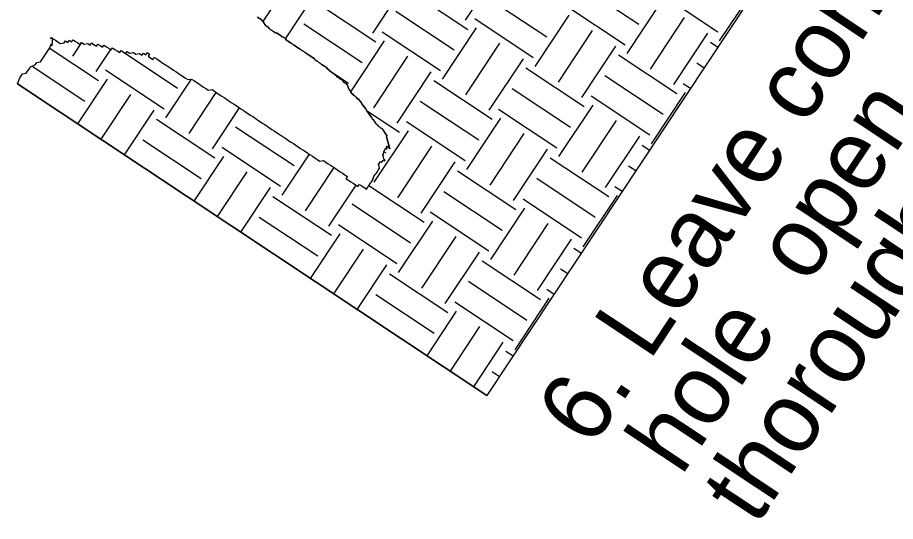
# Model space of a CAD drawing. Extents: x 561231 to 564935, y 589159 to 602519.
# Drawn here: x 564402.6 to 564452.8, y 589700.8 to 589729.7 of the extents above; entities that cross this region are included whole.
import ezdxf

# ---------------------------------------------------------------- set-up
doc = ezdxf.new("R2010")
doc.units = 0
doc.layers.add('Old_Level_1', color=7, linetype='Continuous')

msp = doc.modelspace()

# ---------------------------------------------------------------- linework, layer by layer
at = {"layer": 'Old_Level_1'}
for p, q in [((564452.672, 589743.055), (564429.449, 589708.039)), ((564428.21, 589729.508), (564430.164, 589732.454)), ((564416.632, 589729.431), (564418.251, 589731.874)), ((564422.911, 589728.782), (564424.865, 589731.728)), ((564434.797, 589731.501), (564438.142, 589729.281)), ((564417.91, 589728.453), (564419.589, 589730.986)), ((564425.004, 589731.211), (564428.349, 589728.992)), ((564439.329, 589731.071), (564442.674, 589728.851)), ((564442.775, 589728.328), (564444.728, 589731.274)), ((564419.743, 589730.492), (564423.089, 589728.272)), ((564429.536, 589730.781), (564432.881, 589728.562)), ((564434.015, 589730.322), (564437.361, 589728.103)), ((564437.476, 589727.602), (564439.43, 589730.548)), ((564424.223, 589730.033), (564427.568, 589727.813)), ((564432.201, 589726.86), (564434.154, 589729.806)), ((564418.962, 589729.313), (564422.307, 589727.094)), ((564428.755, 589729.603), (564432.1, 589727.383)), ((564438.814, 589726.715), (564440.768, 589729.66)), ((564423.441, 589728.855), (564426.786, 589726.635)), ((564426.902, 589726.135), (564428.856, 589729.08)), ((564433.539, 589725.972), (564435.493, 589728.918)), ((564404.451, 589728.446), (564404.503, 589728.523)), ((564421.645, 589725.421), (564423.581, 589728.338)), ((564440.152, 589725.827), (564442.106, 589728.772)), ((564404.382, 589727.926), (564407.201, 589726.056)), ((564405.724, 589727.46), (564406.24, 589728.238)), ((564407.062, 589726.572), (564407.897, 589727.832)), ((564408.488, 589727.779), (564411.733, 589725.626)), ((564428.24, 589725.247), (564430.194, 589728.192)), ((564434.877, 589725.085), (564436.83, 589728.031)), ((564442.245, 589728.256), (564442.67, 589727.974)), ((564422.965, 589724.505), (564424.919, 589727.45)), ((564429.578, 589724.359), (564431.532, 589727.304)), ((564436.984, 589727.536), (564440.33, 589725.316)), ((564403.393, 589726.886), (564406.42, 589724.878)), ((564431.671, 589726.788), (564435.016, 589724.568)), ((564441.464, 589727.078), (564441.889, 589726.796)), ((564407.606, 589726.667), (564410.952, 589724.448)), ((564420.429, 589726.643), (564421.526, 589725.916)), ((564424.303, 589723.617), (564426.257, 589726.562)), ((564436.203, 589726.358), (564439.548, 589724.138)), ((564429.449, 589708.039), (564402.563, 589725.877)), ((564402.563, 589725.877), (564429.449, 589708.039)), ((564429.449, 589708.039), (564402.563, 589725.877)), ((564406.012, 589723.588), (564407.708, 589726.144)), ((564411.053, 589723.925), (564412.526, 589726.145)), ((564426.41, 589726.068), (564429.755, 589723.849)), ((564440.682, 589725.899), (564441.107, 589725.618)), ((564407.351, 589722.701), (564409.046, 589725.256)), ((564412.391, 589723.037), (564413.946, 589725.381)), ((564430.89, 589725.609), (564434.235, 589723.39)), ((564438.868, 589722.437), (564440.822, 589725.383)), ((564425.629, 589724.89), (564428.974, 589722.67)), ((564435.422, 589725.179), (564438.767, 589722.96)), ((564408.689, 589721.813), (564410.384, 589724.369)), ((564413.729, 589722.149), (564415.284, 589724.494)), ((564422.55, 589724.356), (564424.442, 589723.1)), ((564430.108, 589724.431), (564433.453, 589722.212)), ((564433.57, 589721.711), (564435.523, 589724.657)), ((564410.523, 589723.852), (564413.868, 589721.632)), ((564428.294, 589720.969), (564430.248, 589723.915)), ((564434.908, 589720.823), (564436.861, 589723.769)), ((564415.055, 589723.422), (564418.4, 589721.202)), ((564424.847, 589723.712), (564428.192, 589721.492)), ((564422.996, 589720.243), (564424.949, 589723.188)), ((564429.632, 589720.082), (564431.586, 589723.027)), ((564436.246, 589719.935), (564438.199, 589722.881)), ((564409.742, 589722.674), (564413.087, 589720.454)), ((564414.273, 589722.244), (564417.618, 589720.024)), ((564424.334, 589719.355), (564426.287, 589722.301)), ((564438.338, 589722.365), (564438.763, 589722.083)), ((564417.72, 589719.501), (564419.275, 589721.846)), ((564423.538, 589722.004), (564423.661, 589721.922)), ((564430.97, 589719.194), (564432.924, 589722.139)), ((564412.68, 589719.165), (564414.375, 589721.721)), ((564425.672, 589718.467), (564427.625, 589721.413)), ((564433.077, 589721.645), (564436.422, 589719.425)), ((564414.018, 589718.277), (564415.713, 589720.833)), ((564419.058, 589718.614), (564420.693, 589721.078)), ((564427.764, 589720.896), (564431.109, 589718.677)), ((564437.557, 589721.186), (564437.982, 589720.905)), ((564432.296, 589720.466), (564435.641, 589718.247)), ((564415.356, 589717.39), (564417.051, 589719.945)), ((564420.396, 589717.726), (564421.951, 589720.07)), ((564422.687, 589720.056), (564425.848, 589717.957)), ((564436.775, 589720.008), (564437.2, 589719.726)), ((564417.19, 589719.429), (564420.535, 589717.209)), ((564426.983, 589719.718), (564430.328, 589717.499)), ((564431.514, 589719.288), (564434.86, 589717.069)), ((564434.961, 589716.546), (564436.915, 589719.492)), ((564421.722, 589718.999), (564425.067, 589716.779)), ((564429.662, 589715.82), (564431.616, 589718.765)), ((564416.409, 589718.25), (564419.754, 589716.031)), ((564426.201, 589718.54), (564429.546, 589716.321)), ((564420.94, 589717.82), (564424.286, 589715.601)), ((564424.387, 589715.078), (564426.341, 589718.024)), ((564431, 589714.932), (564432.954, 589717.877)), ((564419.347, 589714.742), (564421.042, 589717.297)), ((564425.725, 589714.19), (564427.679, 589717.136)), ((564432.338, 589714.044), (564434.292, 589716.99)), ((564420.685, 589713.854), (564422.38, 589716.41)), ((564427.063, 589713.303), (564429.017, 589716.248)), ((564434.431, 589716.473), (564434.856, 589716.192)), ((564429.17, 589715.753), (564432.516, 589713.534)), ((564422.023, 589712.966), (564423.718, 589715.522)), ((564433.65, 589715.295), (564434.074, 589715.013)), ((564423.857, 589715.005), (564427.203, 589712.786)), ((564428.389, 589714.575), (564431.735, 589712.356)), ((564423.076, 589713.827), (564426.421, 589711.608)), ((564432.868, 589714.117), (564433.293, 589713.835)), ((564427.607, 589713.397), (564430.953, 589711.178)), ((564431.054, 589710.655), (564433.007, 589713.601)), ((564426.014, 589710.318), (564427.709, 589712.874)), ((564427.352, 589709.43), (564429.047, 589711.987)), ((564428.69, 589708.543), (564430.385, 589711.099)), ((564430.524, 589710.582), (564430.949, 589710.3)), ((564429.743, 589709.404), (564430.168, 589709.122))]:
    msp.add_line(p, q, dxfattribs=at)
for points in [[(564416.314, 589729.685), (564416.383, 589729.64), (564416.452, 589729.594), (564416.52, 589729.549), (564416.568, 589729.474), (564416.637, 589729.428), (564416.685, 589729.352), (564416.734, 589729.277), (564416.783, 589729.201), (564416.85, 589729.156), (564416.919, 589729.11), (564416.968, 589729.035), (564417.036, 589728.99), (564417.139, 589728.921), (564417.207, 589728.876), (564417.276, 589728.831), (564417.344, 589728.785), (564417.432, 589728.77), (564417.501, 589728.724), (564417.603, 589728.656), (564417.706, 589728.588), (564417.775, 589728.543), (564417.844, 589728.497), (564417.912, 589728.452), (564417.995, 589728.353), (564418.063, 589728.308), (564418.131, 589728.262), (564418.2, 589728.217), (564418.268, 589728.172), (564418.337, 589728.126), (564418.405, 589728.081), (564418.474, 589728.035), (564418.542, 589727.99), (564418.645, 589727.922), (564418.713, 589727.877), (564418.782, 589727.831), (564418.85, 589727.786), (564418.953, 589727.718), (564419.022, 589727.672), (564419.09, 589727.627), (564419.192, 589727.559), (564419.261, 589727.513), (564419.329, 589727.468), (564419.397, 589727.423), (564419.5, 589727.354), (564419.569, 589727.309), (564419.617, 589727.234), (564419.686, 589727.188), (564419.754, 589727.143), (564419.823, 589727.097), (564419.891, 589727.052), (564419.96, 589727.007), (564420.028, 589726.961), (564420.131, 589726.893), (564420.233, 589726.825), (564420.316, 589726.726), (564420.419, 589726.658), (564420.467, 589726.582), (564420.536, 589726.537), (564420.604, 589726.492), (564420.673, 589726.446), (564420.741, 589726.401), (564420.809, 589726.355), (564420.892, 589726.258), (564420.96, 589726.212), (564421.029, 589726.167), (564421.132, 589726.099), (564421.201, 589726.053), (564421.249, 589725.978), (564421.317, 589725.932), (564421.386, 589725.887), (564421.434, 589725.811), (564421.483, 589725.735), (564421.511, 589725.63), (564421.56, 589725.555), (564421.608, 589725.479), (564421.657, 589725.403), (564421.706, 589725.328), (564421.774, 589725.282), (564421.822, 589725.207), (564421.891, 589725.162), (564421.959, 589725.116), (564422.007, 589725.04), (564422.11, 589724.972), (564422.159, 589724.897), (564422.241, 589724.799), (564422.29, 589724.723), (564422.338, 589724.648), (564422.422, 589724.549), (564422.504, 589724.451), (564422.566, 589724.323), (564422.649, 589724.224)], [(564422.649, 589724.224), (564422.566, 589724.323), (564422.504, 589724.451), (564422.422, 589724.549), (564422.338, 589724.648), (564422.29, 589724.723), (564422.241, 589724.799), (564422.159, 589724.897), (564422.11, 589724.972), (564422.007, 589725.04), (564421.959, 589725.116), (564421.891, 589725.162), (564421.822, 589725.207), (564421.774, 589725.282), (564421.706, 589725.328), (564421.657, 589725.403), (564421.608, 589725.479), (564421.56, 589725.555), (564421.511, 589725.63), (564421.483, 589725.735), (564421.434, 589725.811), (564421.386, 589725.887), (564421.317, 589725.932), (564421.249, 589725.978), (564421.201, 589726.053), (564421.132, 589726.099), (564421.029, 589726.167), (564420.96, 589726.212), (564420.892, 589726.258), (564420.809, 589726.355), (564420.741, 589726.401), (564420.673, 589726.446), (564420.604, 589726.492), (564420.536, 589726.537), (564420.467, 589726.582), (564420.419, 589726.658), (564420.316, 589726.726), (564420.233, 589726.825), (564420.131, 589726.893), (564420.028, 589726.961), (564419.96, 589727.007), (564419.891, 589727.052), (564419.823, 589727.097), (564419.754, 589727.143), (564419.686, 589727.188), (564419.617, 589727.234), (564419.569, 589727.309), (564419.5, 589727.354), (564419.397, 589727.423), (564419.329, 589727.468), (564419.261, 589727.513), (564419.192, 589727.559), (564419.09, 589727.627), (564419.022, 589727.672), (564418.953, 589727.718), (564418.85, 589727.786), (564418.782, 589727.831), (564418.713, 589727.877), (564418.645, 589727.922), (564418.542, 589727.99), (564418.474, 589728.035), (564418.405, 589728.081), (564418.337, 589728.126), (564418.268, 589728.172), (564418.2, 589728.217), (564418.131, 589728.262), (564418.063, 589728.308), (564417.995, 589728.353), (564417.912, 589728.452), (564417.844, 589728.497), (564417.775, 589728.543), (564417.706, 589728.588), (564417.603, 589728.656), (564417.501, 589728.724), (564417.432, 589728.77), (564417.344, 589728.785), (564417.276, 589728.831), (564417.207, 589728.876), (564417.139, 589728.921), (564417.036, 589728.99), (564416.968, 589729.035), (564416.919, 589729.11), (564416.85, 589729.156), (564416.783, 589729.201), (564416.734, 589729.277), (564416.685, 589729.352), (564416.637, 589729.428), (564416.568, 589729.474), (564416.52, 589729.549), (564416.452, 589729.594), (564416.383, 589729.64), (564416.314, 589729.685)], [(564404.376, 589727.881), (564404.477, 589728.085), (564404.483, 589728.168), (564404.545, 589728.039), (564404.563, 589728.289), (564404.569, 589728.371), (564404.609, 589728.431), (564404.602, 589728.457)], [(564404.465, 589728.548), (564404.602, 589728.457), (564404.738, 589728.367), (564404.875, 589728.276), (564405.012, 589728.185), (564405.229, 589728.215), (564405.309, 589728.336), (564405.446, 589728.245), (564405.526, 589728.365), (564405.662, 589728.274), (564405.742, 589728.395), (564405.879, 589728.304), (564406.016, 589728.213), (564406.154, 589728.122), (564406.234, 589728.243), (564406.37, 589728.152), (564406.587, 589728.182), (564406.723, 589728.091), (564406.803, 589728.211), (564406.941, 589728.12), (564407.077, 589728.029), (564407.157, 589728.15), (564407.295, 589728.059), (564407.431, 589727.969), (564407.511, 589728.089), (564407.648, 589727.998), (564407.785, 589727.907), (564407.922, 589727.816), (564408.002, 589727.937), (564408.138, 589727.846), (564408.275, 589727.756), (564408.412, 589727.664), (564408.492, 589727.784), (564408.629, 589727.694), (564408.766, 589727.603), (564408.846, 589727.724), (564408.983, 589727.633), (564409.2, 589727.662), (564409.337, 589727.571), (564409.553, 589727.601), (564409.69, 589727.511), (564409.77, 589727.631), (564409.908, 589727.54), (564409.987, 589727.661), (564410.124, 589727.57), (564410.044, 589727.449), (564410.181, 589727.358), (564410.318, 589727.268), (564410.398, 589727.388), (564410.535, 589727.297), (564410.671, 589727.207), (564410.809, 589727.116), (564410.945, 589727.025), (564411.219, 589726.843), (564411.356, 589726.752), (564411.493, 589726.661), (564411.63, 589726.57), (564411.767, 589726.48), (564411.904, 589726.389), (564412.04, 589726.298), (564412.178, 589726.207), (564412.314, 589726.116), (564412.531, 589726.146), (564412.668, 589726.055), (564412.805, 589725.964), (564412.942, 589725.873), (564413.079, 589725.782), (564413.216, 589725.692), (564413.353, 589725.601), (564413.49, 589725.51), (564413.706, 589725.54), (564413.844, 589725.449), (564413.98, 589725.358), (564414.118, 589725.267), (564414.254, 589725.177), (564414.391, 589725.086), (564414.528, 589724.995), (564414.665, 589724.904), (564414.802, 589724.813), (564414.939, 589724.722), (564415.076, 589724.631), (564415.212, 589724.541), (564415.35, 589724.45), (564415.486, 589724.359), (564415.623, 589724.269), (564415.76, 589724.178), (564415.897, 589724.087), (564416.034, 589723.996), (564416.171, 589723.905), (564416.307, 589723.814), (564416.445, 589723.724), (564416.582, 589723.632), (564416.718, 589723.542), (564416.855, 589723.451), (564416.992, 589723.36), (564417.13, 589723.269), (564417.266, 589723.178), (564417.403, 589723.087), (564417.54, 589722.997), (564417.676, 589722.906), (564417.814, 589722.815)], [(564404.465, 589728.548), (564404.602, 589728.457), (564404.738, 589728.367), (564404.875, 589728.276), (564405.012, 589728.185), (564405.229, 589728.215), (564405.309, 589728.336), (564405.446, 589728.245), (564405.526, 589728.365), (564405.662, 589728.274), (564405.742, 589728.395), (564405.879, 589728.304), (564406.016, 589728.213), (564406.154, 589728.122), (564406.234, 589728.243), (564406.37, 589728.152), (564406.587, 589728.182), (564406.723, 589728.091), (564406.803, 589728.211), (564406.941, 589728.12), (564407.077, 589728.029), (564407.157, 589728.15), (564407.295, 589728.059), (564407.431, 589727.969), (564407.511, 589728.089), (564407.648, 589727.998), (564407.785, 589727.907), (564407.922, 589727.816), (564408.002, 589727.937), (564408.138, 589727.846), (564408.275, 589727.756), (564408.412, 589727.664), (564408.492, 589727.784), (564408.629, 589727.694), (564408.766, 589727.603), (564408.846, 589727.724), (564408.983, 589727.633), (564409.2, 589727.662), (564409.337, 589727.571), (564409.553, 589727.601), (564409.69, 589727.511), (564409.77, 589727.631), (564409.908, 589727.54), (564409.987, 589727.661), (564410.124, 589727.57), (564410.044, 589727.449), (564410.181, 589727.358), (564410.318, 589727.268), (564410.398, 589727.388), (564410.535, 589727.297), (564410.671, 589727.207), (564410.809, 589727.116), (564410.945, 589727.025), (564411.219, 589726.843), (564411.356, 589726.752), (564411.493, 589726.661), (564411.63, 589726.57), (564411.767, 589726.48), (564411.904, 589726.389), (564412.04, 589726.298), (564412.178, 589726.207), (564412.314, 589726.116), (564412.531, 589726.146), (564412.668, 589726.055), (564412.805, 589725.964), (564412.942, 589725.873), (564413.079, 589725.782), (564413.216, 589725.692), (564413.353, 589725.601), (564413.49, 589725.51), (564413.706, 589725.54), (564413.844, 589725.449), (564413.98, 589725.358), (564414.118, 589725.267), (564414.254, 589725.177), (564414.391, 589725.086), (564414.528, 589724.995), (564414.665, 589724.904), (564414.802, 589724.813), (564414.939, 589724.722), (564415.076, 589724.631), (564415.212, 589724.541), (564415.35, 589724.45), (564415.486, 589724.359), (564415.623, 589724.269), (564415.76, 589724.178), (564415.897, 589724.087), (564416.034, 589723.996), (564416.171, 589723.905), (564416.307, 589723.814), (564416.445, 589723.724), (564416.582, 589723.632), (564416.718, 589723.542), (564416.855, 589723.451), (564416.992, 589723.36), (564417.13, 589723.269), (564417.266, 589723.178), (564417.403, 589723.087), (564417.54, 589722.997), (564417.676, 589722.906), (564417.814, 589722.815)], [(564402.563, 589725.877), (564402.693, 589726.217), (564402.771, 589726.336), (564402.85, 589726.454), (564403.063, 589726.483), (564403.141, 589726.601), (564403.219, 589726.719), (564403.298, 589726.838), (564403.589, 589726.985), (564403.668, 589727.103), (564403.88, 589727.133), (564403.958, 589727.251), (564404.376, 589727.881)], [(564422.649, 589724.224), (564422.746, 589724.073), (564422.829, 589723.975), (564422.891, 589723.847), (564422.96, 589723.802), (564423.009, 589723.726), (564423.057, 589723.65), (564423.106, 589723.574), (564423.174, 589723.529), (564423.222, 589723.454), (564423.291, 589723.408), (564423.359, 589723.363), (564423.462, 589723.295), (564423.511, 589723.219), (564423.559, 589723.144), (564423.607, 589723.068), (564423.656, 589722.992), (564423.704, 589722.917), (564423.699, 589722.834), (564423.727, 589722.728), (564423.756, 589722.623), (564423.784, 589722.517), (564423.813, 589722.412), (564423.878, 589722.149), (564423.878, 589722.149), (564423.827, 589722.359)], [(564423.827, 589722.359), (564423.878, 589722.149), (564423.878, 589722.149), (564423.813, 589722.412), (564423.784, 589722.517), (564423.756, 589722.623), (564423.727, 589722.728), (564423.699, 589722.834), (564423.704, 589722.917), (564423.656, 589722.992), (564423.607, 589723.068), (564423.559, 589723.144), (564423.511, 589723.219), (564423.462, 589723.295), (564423.359, 589723.363), (564423.291, 589723.408), (564423.222, 589723.454), (564423.174, 589723.529), (564423.106, 589723.574), (564423.057, 589723.65), (564423.009, 589723.726), (564422.96, 589723.802), (564422.891, 589723.847), (564422.829, 589723.975), (564422.746, 589724.073), (564422.649, 589724.224)], [(564417.814, 589722.815), (564418.088, 589722.633), (564418.224, 589722.542), (564418.361, 589722.452), (564418.499, 589722.361), (564418.635, 589722.27), (564418.772, 589722.179), (564418.909, 589722.088), (564419.046, 589721.997), (564419.183, 589721.906), (564419.32, 589721.816), (564419.456, 589721.725), (564419.594, 589721.634), (564419.731, 589721.543), (564419.867, 589721.452), (564420.084, 589721.482), (564420.221, 589721.391), (564420.358, 589721.3), (564420.495, 589721.21), (564420.632, 589721.119), (564420.768, 589721.028), (564420.906, 589720.937), (564421.042, 589720.846), (564421.18, 589720.755), (564421.316, 589720.665), (564421.453, 589720.574), (564421.373, 589720.453), (564421.51, 589720.363), (564421.647, 589720.272), (564421.784, 589720.181), (564421.921, 589720.09), (564422.058, 589719.999), (564422.138, 589720.119), (564422.275, 589720.028), (564422.411, 589719.938), (564422.548, 589719.847), (564422.628, 589719.967), (564422.708, 589720.088), (564422.788, 589720.208), (564422.868, 589720.329), (564422.948, 589720.449)], [(564417.814, 589722.815), (564418.088, 589722.633), (564418.224, 589722.542), (564418.361, 589722.452), (564418.499, 589722.361), (564418.635, 589722.27), (564418.772, 589722.179), (564418.909, 589722.088), (564419.046, 589721.997), (564419.183, 589721.906), (564419.32, 589721.816), (564419.456, 589721.725), (564419.594, 589721.634), (564419.731, 589721.543), (564419.867, 589721.452), (564420.084, 589721.482), (564420.221, 589721.391), (564420.358, 589721.3), (564420.495, 589721.21), (564420.632, 589721.119), (564420.768, 589721.028), (564420.906, 589720.937), (564421.042, 589720.846), (564421.18, 589720.755), (564421.316, 589720.665), (564421.453, 589720.574), (564421.373, 589720.453), (564421.51, 589720.363), (564421.647, 589720.272), (564421.784, 589720.181), (564421.921, 589720.09), (564422.058, 589719.999), (564422.138, 589720.119), (564422.275, 589720.028), (564422.411, 589719.938), (564422.548, 589719.847), (564422.628, 589719.967), (564422.708, 589720.088), (564422.788, 589720.208), (564422.868, 589720.329), (564422.948, 589720.449)], [(564422.868, 589720.329), (564422.974, 589720.562), (564423.014, 589720.623), (564423.054, 589720.683), (564423.094, 589720.743), (564423.174, 589720.863), (564423.213, 589720.924), (564423.254, 589720.984), (564423.293, 589721.044), (564423.265, 589721.15), (564423.237, 589721.256), (564423.277, 589721.316), (564423.317, 589721.376), (564423.357, 589721.437), (564423.424, 589721.392), (564423.464, 589721.451), (564423.504, 589721.512), (564423.573, 589721.466), (564423.613, 589721.526), (564423.544, 589721.572), (564423.516, 589721.677), (564423.487, 589721.783), (564423.527, 589721.843), (564423.539, 589722.009), (564423.619, 589722.13), (564423.659, 589722.19), (564423.727, 589722.144), (564423.699, 589722.25), (564423.739, 589722.31), (564423.878, 589722.149), (564423.878, 589722.149), (564423.739, 589722.31)]]:
    msp.add_lwpolyline(points, dxfattribs=at)

# ---------------------------------------------------------------- texts
for s, p in [('6. Leave compaction ', (564435.45, 589704.98)), (' hole  open.  Water', (564439.752, 589702.127)), (' thoroughly.', (564444.053, 589699.275))]:
    msp.add_text(s, height=4.01452, rotation=56.4482, dxfattribs=at).set_placement(p)

doc.saveas('drawing.dxf')
